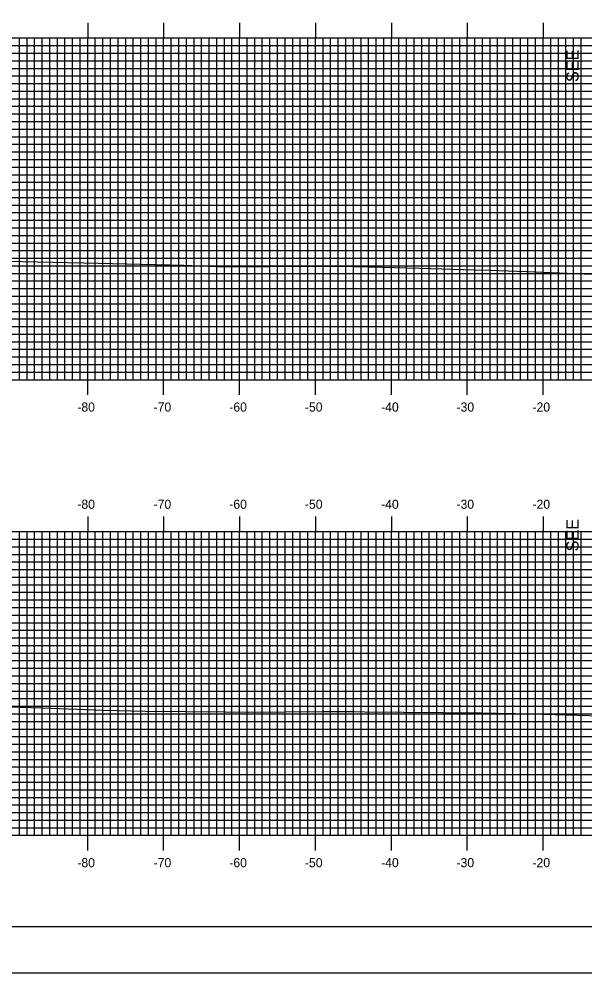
# Model space of a CAD drawing. Extents: x 855297 to 855640, y 364366 to 364586.
# Drawn here: x 855373.7 to 855448.3, y 364365.7 to 364491.3 of the extents above; entities that cross this region are included whole.
import ezdxf

# ---------------------------------------------------------------- set-up
doc = ezdxf.new("R2010")
doc.units = 0
for name, color, linetype in [('ANNOTATION', 7, 'Continuous'), ('BORDER', 7, 'Continuous'), ('H_V ANNOTATION', 7, 'Continuous'), ('MAJOR', 7, 'Continuous'), ('MINOR', 7, 'Continuous'), ('PLOT BOUNDARY', 7, 'Continuous'), ('S_Roadway_Centerline', 7, 'Continuous')]:
    doc.layers.add(name, color=color, linetype=linetype)

msp = doc.modelspace()

# ---------------------------------------------------------------- linework, layer by layer
at = {"layer": 'BORDER'}
msp.add_lwpolyline([(855313.17, 364371.79), (855633.17, 364371.79), (855633.17, 364581.79), (855313.17, 364581.79)], close=True, dxfattribs=at)
at = {"layer": 'MAJOR'}
for p, q in [((855382.77, 364490.79), (855382.77, 364488.79)), ((855392.77, 364490.79), (855392.77, 364488.79)), ((855402.77, 364490.79), (855402.77, 364488.79)), ((855412.77, 364490.79), (855412.77, 364488.79)), ((855422.77, 364490.79), (855422.77, 364488.79)), ((855432.77, 364490.79), (855432.77, 364488.79)), ((855442.77, 364490.79), (855442.77, 364488.79)), ((855322.77, 364488.79), (855602.77, 364488.79)), ((855322.77, 364488.79), (855602.77, 364488.79)), ((855382.77, 364443.79), (855382.77, 364488.79)), ((855392.77, 364443.79), (855392.77, 364488.79)), ((855402.77, 364443.79), (855402.77, 364488.79)), ((855412.77, 364443.79), (855412.77, 364488.79)), ((855422.77, 364443.79), (855422.77, 364488.79)), ((855432.77, 364443.79), (855432.77, 364488.79)), ((855442.77, 364443.79), (855442.77, 364488.79)), ((855322.77, 364483.79), (855602.77, 364483.79)), ((855322.77, 364478.79), (855602.77, 364478.79)), ((855322.77, 364473.79), (855602.77, 364473.79)), ((855322.77, 364468.79), (855602.77, 364468.79)), ((855322.77, 364463.79), (855602.77, 364463.79)), ((855322.77, 364458.79), (855602.77, 364458.79)), ((855322.77, 364453.79), (855602.77, 364453.79)), ((855322.77, 364448.79), (855602.77, 364448.79)), ((855322.77, 364443.79), (855602.77, 364443.79)), ((855322.77, 364443.79), (855602.77, 364443.79)), ((855382.77, 364441.78), (855382.77, 364443.79)), ((855392.77, 364441.78), (855392.77, 364443.79)), ((855402.77, 364441.78), (855402.77, 364443.79)), ((855412.77, 364441.78), (855412.77, 364443.79)), ((855422.77, 364441.78), (855422.77, 364443.79)), ((855432.77, 364441.78), (855432.77, 364443.79)), ((855442.77, 364441.78), (855442.77, 364443.79)), ((855382.77, 364425.79), (855382.77, 364423.79)), ((855392.77, 364425.79), (855392.77, 364423.79)), ((855402.77, 364425.79), (855402.77, 364423.79)), ((855412.77, 364425.79), (855412.77, 364423.79)), ((855422.77, 364425.79), (855422.77, 364423.79)), ((855432.77, 364425.79), (855432.77, 364423.79)), ((855442.77, 364425.79), (855442.77, 364423.79)), ((855322.77, 364423.79), (855602.77, 364423.79)), ((855322.77, 364423.79), (855602.77, 364423.79)), ((855382.77, 364383.79), (855382.77, 364423.79)), ((855392.77, 364383.79), (855392.77, 364423.79)), ((855402.77, 364383.79), (855402.77, 364423.79)), ((855412.77, 364383.79), (855412.77, 364423.79)), ((855422.77, 364383.79), (855422.77, 364423.79)), ((855432.77, 364383.79), (855432.77, 364423.79)), ((855442.77, 364383.79), (855442.77, 364423.79)), ((855322.77, 364418.79), (855602.77, 364418.79)), ((855322.77, 364413.79), (855602.77, 364413.79)), ((855322.77, 364408.79), (855602.77, 364408.79)), ((855322.77, 364403.79), (855602.77, 364403.79)), ((855322.77, 364398.79), (855602.77, 364398.79)), ((855322.77, 364393.79), (855602.77, 364393.79)), ((855322.77, 364388.79), (855602.77, 364388.79)), ((855322.77, 364383.79), (855602.77, 364383.79)), ((855322.77, 364383.79), (855602.77, 364383.79)), ((855382.77, 364381.78), (855382.77, 364383.79)), ((855392.77, 364381.78), (855392.77, 364383.79)), ((855402.77, 364381.78), (855402.77, 364383.79)), ((855412.77, 364381.78), (855412.77, 364383.79)), ((855422.77, 364381.78), (855422.77, 364383.79)), ((855432.77, 364381.78), (855432.77, 364383.79)), ((855442.77, 364381.78), (855442.77, 364383.79))]:
    msp.add_line(p, q, dxfattribs=at)
at = {"layer": 'MINOR'}
for p, q in [((855322.77, 364487.79), (855602.77, 364487.79)), ((855373.77, 364443.79), (855373.77, 364488.79)), ((855374.77, 364443.79), (855374.77, 364488.79)), ((855375.77, 364443.79), (855375.77, 364488.79)), ((855376.77, 364443.79), (855376.77, 364488.79)), ((855377.77, 364443.79), (855377.77, 364488.79)), ((855378.77, 364443.79), (855378.77, 364488.79)), ((855379.77, 364443.79), (855379.77, 364488.79)), ((855380.77, 364443.79), (855380.77, 364488.79)), ((855381.77, 364443.79), (855381.77, 364488.79)), ((855383.77, 364443.79), (855383.77, 364488.79)), ((855384.77, 364443.79), (855384.77, 364488.79)), ((855385.77, 364443.79), (855385.77, 364488.79)), ((855386.77, 364443.79), (855386.77, 364488.79)), ((855387.77, 364443.79), (855387.77, 364488.79)), ((855388.77, 364443.79), (855388.77, 364488.79)), ((855389.77, 364443.79), (855389.77, 364488.79)), ((855390.77, 364443.79), (855390.77, 364488.79)), ((855391.77, 364443.79), (855391.77, 364488.79)), ((855393.77, 364443.79), (855393.77, 364488.79)), ((855394.77, 364443.79), (855394.77, 364488.79)), ((855395.77, 364443.79), (855395.77, 364488.79)), ((855396.77, 364443.79), (855396.77, 364488.79)), ((855397.77, 364443.79), (855397.77, 364488.79)), ((855398.77, 364443.79), (855398.77, 364488.79)), ((855399.77, 364443.79), (855399.77, 364488.79)), ((855400.77, 364443.79), (855400.77, 364488.79)), ((855401.77, 364443.79), (855401.77, 364488.79)), ((855403.77, 364443.79), (855403.77, 364488.79)), ((855404.77, 364443.79), (855404.77, 364488.79)), ((855405.77, 364443.79), (855405.77, 364488.79)), ((855406.77, 364443.79), (855406.77, 364488.79)), ((855407.77, 364443.79), (855407.77, 364488.79)), ((855408.77, 364443.79), (855408.77, 364488.79)), ((855409.77, 364443.79), (855409.77, 364488.79)), ((855410.77, 364443.79), (855410.77, 364488.79)), ((855411.77, 364443.79), (855411.77, 364488.79)), ((855413.77, 364443.79), (855413.77, 364488.79)), ((855414.77, 364443.79), (855414.77, 364488.79)), ((855415.77, 364443.79), (855415.77, 364488.79)), ((855416.77, 364443.79), (855416.77, 364488.79)), ((855417.77, 364443.79), (855417.77, 364488.79)), ((855418.77, 364443.79), (855418.77, 364488.79)), ((855419.77, 364443.79), (855419.77, 364488.79)), ((855420.77, 364443.79), (855420.77, 364488.79)), ((855421.77, 364443.79), (855421.77, 364488.79)), ((855423.77, 364443.79), (855423.77, 364488.79)), ((855424.77, 364443.79), (855424.77, 364488.79)), ((855425.77, 364443.79), (855425.77, 364488.79)), ((855426.77, 364443.79), (855426.77, 364488.79)), ((855427.77, 364443.79), (855427.77, 364488.79)), ((855428.77, 364443.79), (855428.77, 364488.79)), ((855429.77, 364443.79), (855429.77, 364488.79)), ((855430.77, 364443.79), (855430.77, 364488.79)), ((855431.77, 364443.79), (855431.77, 364488.79)), ((855433.77, 364443.79), (855433.77, 364488.79)), ((855434.77, 364443.79), (855434.77, 364488.79)), ((855435.77, 364443.79), (855435.77, 364488.79)), ((855436.77, 364443.79), (855436.77, 364488.79)), ((855437.77, 364443.79), (855437.77, 364488.79)), ((855438.77, 364443.79), (855438.77, 364488.79)), ((855439.77, 364443.79), (855439.77, 364488.79)), ((855440.77, 364443.79), (855440.77, 364488.79)), ((855441.77, 364443.79), (855441.77, 364488.79)), ((855443.77, 364443.79), (855443.77, 364488.79)), ((855444.77, 364443.79), (855444.77, 364488.79)), ((855445.77, 364443.79), (855445.77, 364488.79)), ((855446.77, 364443.79), (855446.77, 364488.79)), ((855447.77, 364443.79), (855447.77, 364488.79)), ((855322.77, 364486.79), (855602.77, 364486.79)), ((855322.77, 364485.79), (855602.77, 364485.79)), ((855322.77, 364484.79), (855602.77, 364484.79)), ((855322.77, 364482.79), (855602.77, 364482.79)), ((855322.77, 364481.79), (855602.77, 364481.79)), ((855322.77, 364480.79), (855602.77, 364480.79)), ((855322.77, 364479.79), (855602.77, 364479.79)), ((855322.77, 364477.79), (855602.77, 364477.79)), ((855322.77, 364476.79), (855602.77, 364476.79)), ((855322.77, 364475.79), (855602.77, 364475.79)), ((855322.77, 364474.79), (855602.77, 364474.79)), ((855322.77, 364472.79), (855602.77, 364472.79)), ((855322.77, 364471.79), (855602.77, 364471.79)), ((855322.77, 364470.79), (855602.77, 364470.79)), ((855322.77, 364469.79), (855602.77, 364469.79)), ((855322.77, 364467.79), (855602.77, 364467.79)), ((855322.77, 364466.79), (855602.77, 364466.79)), ((855322.77, 364465.79), (855602.77, 364465.79)), ((855322.77, 364464.79), (855602.77, 364464.79)), ((855322.77, 364462.79), (855602.77, 364462.79)), ((855322.77, 364461.79), (855602.77, 364461.79)), ((855322.77, 364460.79), (855602.77, 364460.79)), ((855322.77, 364459.79), (855602.77, 364459.79)), ((855322.77, 364457.79), (855602.77, 364457.79)), ((855322.77, 364456.79), (855602.77, 364456.79)), ((855322.77, 364455.79), (855602.77, 364455.79)), ((855322.77, 364454.79), (855602.77, 364454.79)), ((855322.77, 364452.79), (855602.77, 364452.79)), ((855322.77, 364451.79), (855602.77, 364451.79)), ((855322.77, 364450.79), (855602.77, 364450.79)), ((855322.77, 364449.79), (855602.77, 364449.79)), ((855322.77, 364447.79), (855602.77, 364447.79)), ((855322.77, 364446.79), (855602.77, 364446.79)), ((855322.77, 364445.79), (855602.77, 364445.79)), ((855322.77, 364444.79), (855602.77, 364444.79)), ((855373.77, 364383.79), (855373.77, 364423.79)), ((855374.77, 364383.79), (855374.77, 364423.79)), ((855375.77, 364383.79), (855375.77, 364423.79)), ((855376.77, 364383.79), (855376.77, 364423.79)), ((855377.77, 364383.79), (855377.77, 364423.79)), ((855378.77, 364383.79), (855378.77, 364423.79)), ((855379.77, 364383.79), (855379.77, 364423.79)), ((855380.77, 364383.79), (855380.77, 364423.79)), ((855381.77, 364383.79), (855381.77, 364423.79)), ((855383.77, 364383.79), (855383.77, 364423.79)), ((855384.77, 364383.79), (855384.77, 364423.79)), ((855385.77, 364383.79), (855385.77, 364423.79)), ((855386.77, 364383.79), (855386.77, 364423.79)), ((855387.77, 364383.79), (855387.77, 364423.79)), ((855388.77, 364383.79), (855388.77, 364423.79)), ((855389.77, 364383.79), (855389.77, 364423.79)), ((855390.77, 364383.79), (855390.77, 364423.79)), ((855391.77, 364383.79), (855391.77, 364423.79)), ((855393.77, 364383.79), (855393.77, 364423.79)), ((855394.77, 364383.79), (855394.77, 364423.79)), ((855395.77, 364383.79), (855395.77, 364423.79)), ((855396.77, 364383.79), (855396.77, 364423.79)), ((855397.77, 364383.79), (855397.77, 364423.79)), ((855398.77, 364383.79), (855398.77, 364423.79)), ((855399.77, 364383.79), (855399.77, 364423.79)), ((855400.77, 364383.79), (855400.77, 364423.79)), ((855401.77, 364383.79), (855401.77, 364423.79)), ((855403.77, 364383.79), (855403.77, 364423.79)), ((855404.77, 364383.79), (855404.77, 364423.79)), ((855405.77, 364383.79), (855405.77, 364423.79)), ((855406.77, 364383.79), (855406.77, 364423.79)), ((855407.77, 364383.79), (855407.77, 364423.79)), ((855408.77, 364383.79), (855408.77, 364423.79)), ((855409.77, 364383.79), (855409.77, 364423.79)), ((855410.77, 364383.79), (855410.77, 364423.79)), ((855411.77, 364383.79), (855411.77, 364423.79)), ((855413.77, 364383.79), (855413.77, 364423.79)), ((855414.77, 364383.79), (855414.77, 364423.79)), ((855415.77, 364383.79), (855415.77, 364423.79)), ((855416.77, 364383.79), (855416.77, 364423.79)), ((855417.77, 364383.79), (855417.77, 364423.79)), ((855418.77, 364383.79), (855418.77, 364423.79)), ((855419.77, 364383.79), (855419.77, 364423.79)), ((855420.77, 364383.79), (855420.77, 364423.79)), ((855421.77, 364383.79), (855421.77, 364423.79)), ((855423.77, 364383.79), (855423.77, 364423.79)), ((855424.77, 364383.79), (855424.77, 364423.79)), ((855425.77, 364383.79), (855425.77, 364423.79)), ((855426.77, 364383.79), (855426.77, 364423.79)), ((855427.77, 364383.79), (855427.77, 364423.79)), ((855428.77, 364383.79), (855428.77, 364423.79)), ((855429.77, 364383.79), (855429.77, 364423.79)), ((855430.77, 364383.79), (855430.77, 364423.79)), ((855431.77, 364383.79), (855431.77, 364423.79)), ((855433.77, 364383.79), (855433.77, 364423.79)), ((855434.77, 364383.79), (855434.77, 364423.79)), ((855435.77, 364383.79), (855435.77, 364423.79)), ((855436.77, 364383.79), (855436.77, 364423.79)), ((855437.77, 364383.79), (855437.77, 364423.79)), ((855438.77, 364383.79), (855438.77, 364423.79)), ((855439.77, 364383.79), (855439.77, 364423.79)), ((855440.77, 364383.79), (855440.77, 364423.79)), ((855441.77, 364383.79), (855441.77, 364423.79)), ((855443.77, 364383.79), (855443.77, 364423.79)), ((855444.77, 364383.79), (855444.77, 364423.79)), ((855445.77, 364383.79), (855445.77, 364423.79)), ((855446.77, 364383.79), (855446.77, 364423.79)), ((855447.77, 364383.79), (855447.77, 364423.79)), ((855322.77, 364422.79), (855602.77, 364422.79)), ((855322.77, 364421.79), (855602.77, 364421.79)), ((855322.77, 364420.79), (855602.77, 364420.79)), ((855322.77, 364419.79), (855602.77, 364419.79)), ((855322.77, 364417.79), (855602.77, 364417.79)), ((855322.77, 364416.79), (855602.77, 364416.79)), ((855322.77, 364415.79), (855602.77, 364415.79)), ((855322.77, 364414.79), (855602.77, 364414.79)), ((855322.77, 364412.79), (855602.77, 364412.79)), ((855322.77, 364411.79), (855602.77, 364411.79)), ((855322.77, 364410.79), (855602.77, 364410.79)), ((855322.77, 364409.79), (855602.77, 364409.79)), ((855322.77, 364407.79), (855602.77, 364407.79)), ((855322.77, 364406.79), (855602.77, 364406.79)), ((855322.77, 364405.79), (855602.77, 364405.79)), ((855322.77, 364404.79), (855602.77, 364404.79)), ((855322.77, 364402.79), (855602.77, 364402.79)), ((855322.77, 364401.79), (855602.77, 364401.79)), ((855322.77, 364400.79), (855602.77, 364400.79)), ((855322.77, 364399.79), (855602.77, 364399.79)), ((855322.77, 364397.79), (855602.77, 364397.79)), ((855322.77, 364396.79), (855602.77, 364396.79)), ((855322.77, 364395.79), (855602.77, 364395.79)), ((855322.77, 364394.79), (855602.77, 364394.79)), ((855322.77, 364392.79), (855602.77, 364392.79)), ((855322.77, 364391.79), (855602.77, 364391.79)), ((855322.77, 364390.79), (855602.77, 364390.79)), ((855322.77, 364389.79), (855602.77, 364389.79)), ((855322.77, 364387.79), (855602.77, 364387.79)), ((855322.77, 364386.79), (855602.77, 364386.79)), ((855322.77, 364385.79), (855602.77, 364385.79)), ((855322.77, 364384.79), (855602.77, 364384.79))]:
    msp.add_line(p, q, dxfattribs=at)
at = {"layer": 'PLOT BOUNDARY'}
msp.add_lwpolyline([(855296.98, 364365.67), (855636.98, 364365.67), (855636.98, 364585.67), (855296.98, 364585.67)], close=True, dxfattribs=at)
at = {"layer": 'S_Roadway_Centerline'}
for points in [[(855322.77, 364459.99), (855329.86, 364459.7), (855332.04, 364459.61), (855337.52, 364459.53), (855344.27, 364459.55), (855347.12, 364459.51), (855357, 364459.49), (855364.14, 364459.57), (855380.13, 364459.21), (855382.25, 364459.16), (855395.43, 364458.89), (855400.7, 364458.66), (855412.86, 364458.72), (855417.75, 364458.68), (855419.83, 364458.65), (855426.52, 364458.47), (855433.73, 364458.26), (855435.74, 364458.22), (855440.56, 364458.03), (855452.48, 364457.55)], [(855322.77, 364400.75), (855333.36, 364400.94), (855334.68, 364400.95), (855341.84, 364400.88), (855348.82, 364400.81), (855350.16, 364400.79), (855362.89, 364400.79), (855367.46, 364400.82), (855376.76, 364400.58), (855384.77, 364400.28), (855390.32, 364400.13), (855400.94, 364400.04), (855404, 364400.01), (855413.66, 364400.08), (855417.86, 364400.11), (855419.28, 364400.07), (855434.62, 364399.9), (855441.38, 364399.78), (855451.75, 364399.5)]]:
    msp.add_lwpolyline(points, dxfattribs=at)

# ---------------------------------------------------------------- texts
at = {"layer": 'ANNOTATION'}
for p in [(855447.43, 364482.98), (855447.43, 364421.18)]:
    msp.add_text('SEE', height=1.6, rotation=90, dxfattribs=at).set_placement(p)
at = {"layer": 'H_V ANNOTATION'}
for s, p in [('-80', (855381.4, 364439.59)), ('-70', (855391.45, 364439.59)), ('-60', (855401.42, 364439.59)), ('-50', (855411.38, 364439.59)), ('-40', (855421.42, 364439.59)), ('-30', (855431.35, 364439.59)), ('-20', (855441.36, 364439.59)), ('-80', (855381.4, 364426.79)), ('-70', (855391.45, 364426.79)), ('-60', (855401.42, 364426.79)), ('-50', (855411.38, 364426.79)), ('-40', (855421.42, 364426.79)), ('-30', (855431.35, 364426.79)), ('-20', (855441.36, 364426.79)), ('-80', (855381.4, 364379.59)), ('-70', (855391.45, 364379.59)), ('-60', (855401.42, 364379.59)), ('-50', (855411.38, 364379.59)), ('-40', (855421.42, 364379.59)), ('-30', (855431.35, 364379.59)), ('-20', (855441.36, 364379.59))]:
    msp.add_text(s, height=1.2, dxfattribs=at).set_placement(p)

doc.saveas('drawing.dxf')
